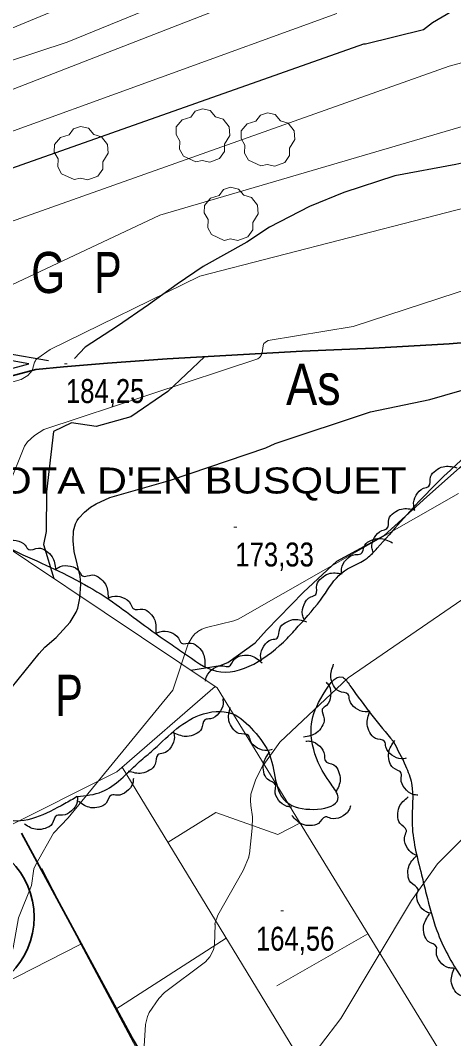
# Model space of a CAD drawing. Extents: x 483847 to 488453, y 4383581 to 4386795.
# Drawn here: x 484564.9 to 484722.9, y 4384859.8 to 4385231.8 of the extents above; entities that cross this region are included whole.
import ezdxf
from ezdxf.enums import TextEntityAlignment as Align

# ---------------------------------------------------------------- set-up
doc = ezdxf.new("R2010")
doc.units = 0
doc.header["$LTSCALE"] = 3.8
doc.linetypes.add('LONG_DASHED', pattern=[7.5, 6, -1.5])
doc.linetypes.add('MEDIUM_DASHED', pattern=[4.5, 3, -1.5])
for name, color, linetype, lineweight in [('25', 7, 'LONG_DASHED', 25), ('27', 7, 'Continuous', 25), ('29', 7, 'Continuous', 13), ('38', 7, 'Continuous', 25), ('51', 7, 'Continuous', 13), ('6', 7, 'Continuous', 35), ('7', 7, 'Continuous', 13), ('8', 7, 'Continuous', 25), ('9', 7, 'Continuous', 13)]:
    doc.layers.add(name, color=color, linetype=linetype, lineweight=lineweight)
doc.layers.add('31', color=7, linetype='Continuous')
doc.layers.add('5', color=7, linetype='Continuous')

msp = doc.modelspace()

# ---------------------------------------------------------------- linework, layer by layer
at = {"layer": '25'}
for points in [[(484744.44, 4385184.53), (484734, 4385181.44), (484723.74, 4385179.06), (484701.41, 4385174.97), (484682.91, 4385168.93), (484670.34, 4385163.77), (484655.79, 4385156.28), (484647.45, 4385150.74), (484631.56, 4385141.82), (484622.13, 4385135.45), (484611.64, 4385127.81), (484600.31, 4385120.09), (484588.51, 4385112.44), (484584.62, 4385108.22)], [(484697.53, 4385043.59), (484713.19, 4385057.72), (484725, 4385068.37), (484738.93, 4385080.47), (484742.6, 4385083.33), (484759.76, 4385096.91), (484768.44, 4385105.31), (484785.43, 4385118.09)], [(484632.01, 4385108.9), (484618.69, 4385096.14), (484605.21, 4385086.95), (484592.55, 4385083.44), (484583.56, 4385084.74), (484577.01, 4385081.55), (484574.39, 4385059.51), (484574.32, 4385045.07), (484573.37, 4385040.36), (484577.15, 4385027.85)], [(484627.12, 4384994.38), (484637.82, 4384996.16), (484640.58, 4384997.21), (484650.58, 4385004.37), (484654.69, 4385009.08), (484668.18, 4385022.91), (484680.36, 4385034.21), (484697.56, 4385043.61)]]:
    msp.add_lwpolyline(points, dxfattribs=at)
at = {"layer": '27'}
for points in [[(484126.09, 4384902.79), (484170.42, 4384940.62), (484186.72, 4384951.71), (484191.28, 4384949.75), (484195.85, 4384942.58), (484195.2, 4384850.61), (484198.46, 4384849.31), (484203.02, 4384849.96), (484206.93, 4384851.91), (484210.19, 4384864.31), (484210.19, 4384911.92), (484211.5, 4384943.23), (484214.1, 4384965.41), (484221.93, 4384987.58), (484217.36, 4384992.8), (484210.19, 4384992.8), (484135.22, 4384984.97), (484130.65, 4384988.89), (484126.09, 4384997.37), (484121.53, 4385047.59), (484126.09, 4385059.33), (484133.91, 4385067.16), (484151.52, 4385069.77), (484197.15, 4385061.94), (484225.84, 4385054.77), (484236.92, 4385050.2), (484251.92, 4385040.42), (484272.13, 4385031.28), (484285.82, 4385029.98), (484298.2, 4385029.33), (484332.11, 4385039.76), (484352.32, 4385052.16), (484358.18, 4385050.2), (484379.05, 4385045.63), (484396, 4385044.98), (484413.6, 4385057.38), (484413.6, 4385076.29), (484415.56, 4385110.21), (484421.42, 4385117.38), (484434.46, 4385125.86), (484452.06, 4385127.17), (484517.26, 4385131.08), (484535.51, 4385145.43), (484539.43, 4385153.26), (484534.21, 4385163.04), (484527.69, 4385172.17), (484530.3, 4385183.26), (484560.29, 4385234.79), (484583.76, 4385251.75), (484588.32, 4385252.4), (484664.6, 4385247.83), (484699.15, 4385252.4), (484722.1, 4385262.06)], [(484700.82, 4384968.46), (484705.41, 4384959.43), (484707.55, 4384953.09), (484707.74, 4384939), (484711.22, 4384919.64), (484712.92, 4384912.69), (484716.8, 4384899.3), (484725.74, 4384882.24), (484736.07, 4384869.4), (484745.06, 4384860.93), (484750.28, 4384857.29), (484764, 4384859.06), (484770.61, 4384868.01), (484777.26, 4384873.01), (484781.91, 4384878.36), (484796.36, 4384884.03), (484807.44, 4384882.61), (484816.96, 4384899.83), (484823.17, 4384919.01), (484826.91, 4384930.91), (484828.12, 4384939.98), (484830.31, 4384967.09), (484821.85, 4384985.57), (484819.78, 4384989.11), (484816.96, 4385006.72), (484804.17, 4385008.65), (484792.01, 4385000.71), (484785.16, 4385000.41), (484783.76, 4385012.32), (484786.61, 4385017.19), (484802.93, 4385029.89), (484816.99, 4385036.63), (484831.62, 4385042.77), (484831.85, 4385052.42), (484828.77, 4385053.4), (484819, 4385062.66), (484818.83, 4385065.3), (484812.25, 4385067.05), (484801.05, 4385062.91), (484791.28, 4385056.88), (484772.36, 4385043.62), (484767.88, 4385041.12), (484748.05, 4385041.41), (484745.09, 4385048.67), (484744.52, 4385049.12), (484744.55, 4385052.7), (484748.79, 4385058.77), (484748.64, 4385063.3), (484740.19, 4385063.82), (484742.63, 4385070.57), (484763.21, 4385085.99), (484768.65, 4385092.72), (484762.05, 4385095.21), (484749.87, 4385090.39), (484739.63, 4385082.24), (484731.52, 4385075.98), (484695.06, 4385038.96)], [(484708.79, 4385052.9), (484708.34, 4385054.62), (484709.24, 4385058.3), (484711.91, 4385060.86), (484713.83, 4385061.57), (484714.51, 4385065.06), (484716.38, 4385067.39), (484719.08, 4385068.74), (484724.03, 4385068.36)], [(484693.57, 4385037.45), (484693.12, 4385039.17), (484694.02, 4385042.85), (484696.69, 4385045.4), (484698.61, 4385046.12), (484699.29, 4385049.61), (484701.16, 4385051.93), (484703.86, 4385053.28), (484708.81, 4385052.9)], [(484585.59, 4384948.21), (484580.97, 4384945.58), (484559.8, 4384939.88), (484549.69, 4384946.4), (484536.11, 4384951.35), (484524.15, 4384948.87), (484511.2, 4384941.93), (484493.5, 4384930.76), (484470.97, 4384918.5), (484448.03, 4384909.24), (484426.95, 4384899.71), (484410.49, 4384892.92), (484385.23, 4384895.42), (484388.62, 4384909.57), (484391.63, 4384936.1), (484393.56, 4384945.05), (484404.24, 4384952.03), (484417.14, 4384934.99), (484427.13, 4384928.88), (484438.84, 4384933.79), (484461.12, 4384944.82), (484483.93, 4384957.41), (484496.79, 4384964.37), (484506.7, 4384969.76), (484524.49, 4384977.21), (484535.34, 4384990.46), (484526.45, 4385001.52), (484515.95, 4385002.96), (484498.76, 4384998.27), (484491.46, 4385002.45), (484491.28, 4385010.27), (484510.27, 4385023.11), (484522.64, 4385031.97), (484541.56, 4385045.7), (484558.82, 4385039.91), (484572.59, 4385033.52), (484597.25, 4385020.22), (484607.27, 4385012.89), (484618.82, 4385004.61), (484624.36, 4385000.79), (484636.37, 4384994.07), (484662.16, 4385005.98), (484666.23, 4385010.44), (484675.39, 4385021.46), (484682.04, 4385029.89), (484691.36, 4385035.38), (484695.06, 4385038.96)], [(484558.14, 4385040.38), (484559.61, 4385041.38), (484563.38, 4385041.73), (484566.67, 4385040.05), (484567.98, 4385038.47), (484571.49, 4385038.98), (484574.31, 4385037.97), (484576.47, 4385035.86), (484577.73, 4385031.07)], [(484682.03, 4385029.7), (484682, 4385031.47), (484683.78, 4385034.83), (484686.99, 4385036.65), (484689.03, 4385036.88), (484690.53, 4385040.1), (484692.91, 4385041.9), (484695.86, 4385042.55), (484700.57, 4385040.98)], [(484577.86, 4385031.31), (484579.38, 4385032.22), (484583.17, 4385032.37), (484586.36, 4385030.51), (484587.58, 4385028.86), (484591.12, 4385029.18), (484593.88, 4385028.02), (484595.92, 4385025.8), (484596.92, 4385020.94)], [(484668.36, 4385012.98), (484667.76, 4385014.64), (484668.34, 4385018.39), (484670.78, 4385021.16), (484672.64, 4385022.04), (484673.01, 4385025.58), (484674.67, 4385028.06), (484677.25, 4385029.63), (484682.21, 4385029.68)], [(484596.75, 4385020.63), (484598.38, 4385021.33), (484602.16, 4385020.96), (484605.06, 4385018.68), (484606.05, 4385016.88), (484609.6, 4385016.71), (484612.17, 4385015.2), (484613.89, 4385012.71), (484614.22, 4385007.76)], [(484652.85, 4384997.87), (484652.52, 4384999.61), (484653.71, 4385003.22), (484656.56, 4385005.56), (484658.54, 4385006.12), (484659.47, 4385009.55), (484661.51, 4385011.73), (484664.31, 4385012.87), (484669.22, 4385012.12)], [(484614.19, 4385007.71), (484615.8, 4385008.47), (484619.58, 4385008.24), (484622.57, 4385006.07), (484623.62, 4385004.31), (484627.17, 4385004.27), (484629.8, 4385002.85), (484631.61, 4385000.43), (484632.12, 4384995.49)], [(484632.43, 4384990.4), (484632.81, 4384992.13), (484635.31, 4384994.99), (484638.86, 4384996.02), (484640.9, 4384995.77), (484643.1, 4384998.56), (484645.83, 4384999.76), (484648.85, 4384999.72), (484653.07, 4384997.1)], [(484692.39, 4384979.38), (484690.63, 4384979.16), (484687.1, 4384980.55), (484684.94, 4384983.54), (484684.49, 4384985.55), (484681.12, 4384986.69), (484679.07, 4384988.85), (484678.1, 4384991.72), (484679.14, 4384996.56)], [(484585.59, 4384948.21), (484594.7, 4384950.05), (484607.73, 4384960.45), (484612.68, 4384964.74), (484630.28, 4384977.98), (484642.06, 4384978.57), (484649.94, 4384972.27), (484655.9, 4384963.29), (484663.95, 4384945.01), (484680.79, 4384948.01), (484678.22, 4384952.8), (484673.51, 4384960.71), (484670.94, 4384973.59), (484674.44, 4384984.01), (484682.46, 4384991.8), (484685.09, 4384988.84), (484700.82, 4384968.46)], [(484676.39, 4384990.05), (484677.47, 4384988.64), (484678.03, 4384984.89), (484676.53, 4384981.52), (484675.02, 4384980.13), (484675.72, 4384976.64), (484674.87, 4384973.78), (484672.88, 4384971.5), (484668.16, 4384969.98)], [(484638.7, 4384983.94), (484638.85, 4384982.17), (484637.31, 4384978.7), (484634.23, 4384976.66), (484632.21, 4384976.3), (484630.94, 4384972.98), (484628.68, 4384971.02), (484625.78, 4384970.17), (484620.98, 4384971.41)], [(484656.73, 4384965.48), (484655.02, 4384965.04), (484651.34, 4384965.97), (484648.81, 4384968.65), (484648.1, 4384970.58), (484644.62, 4384971.28), (484642.3, 4384973.17), (484640.97, 4384975.88), (484641.39, 4384980.83)], [(484705.64, 4384962.21), (484703.88, 4384961.99), (484700.36, 4384963.38), (484698.19, 4384966.37), (484697.74, 4384968.38), (484694.37, 4384969.51), (484692.32, 4384971.68), (484691.35, 4384974.55), (484692.39, 4384979.39)], [(484620.73, 4384971.72), (484621.06, 4384969.98), (484619.86, 4384966.37), (484617, 4384964.04), (484615.03, 4384963.48), (484614.08, 4384960.05), (484612.03, 4384957.88), (484609.23, 4384956.75), (484604.33, 4384957.52)], [(484668.97, 4384968.5), (484670.74, 4384968.49), (484674.06, 4384966.65), (484675.82, 4384963.41), (484676.01, 4384961.37), (484679.2, 4384959.8), (484680.96, 4384957.39), (484681.55, 4384954.42), (484679.89, 4384949.75)], [(484709.88, 4384948.77), (484708.13, 4384949.01), (484705.07, 4384951.26), (484703.75, 4384954.71), (484703.83, 4384956.76), (484700.87, 4384958.73), (484699.44, 4384961.35), (484699.24, 4384964.37), (484701.49, 4384968.78)], [(484663.8, 4384944.38), (484662.05, 4384944.67), (484659.06, 4384946.99), (484657.82, 4384950.47), (484657.95, 4384952.52), (484655.04, 4384954.56), (484653.68, 4384957.22), (484653.55, 4384960.24), (484655.91, 4384964.6)], [(484606.12, 4384954.87), (484605.89, 4384953.11), (484603.64, 4384950.06), (484600.2, 4384948.72), (484598.14, 4384948.8), (484596.18, 4384945.84), (484593.56, 4384944.4), (484590.55, 4384944.19), (484586.13, 4384946.44)], [(484585.7, 4384948.01), (484585.6, 4384946.23), (484583.58, 4384943.02), (484580.25, 4384941.43), (484578.2, 4384941.36), (484576.46, 4384938.26), (484573.96, 4384936.63), (484570.96, 4384936.2), (484566.39, 4384938.11)], [(484709.71, 4384926.71), (484708.06, 4384927.35), (484705.62, 4384930.27), (484705.15, 4384933.93), (484705.71, 4384935.9), (484703.3, 4384938.51), (484702.54, 4384941.4), (484703.05, 4384944.38), (484706.29, 4384948.14)], [(484685.34, 4384944.88), (484684.7, 4384943.22), (484681.8, 4384940.77), (484678.14, 4384940.28), (484676.17, 4384940.83), (484673.57, 4384938.4), (484670.69, 4384937.62), (484667.71, 4384938.12), (484663.93, 4384941.33)], [(484714.7, 4384905.6), (484713, 4384906.1), (484710.32, 4384908.79), (484709.53, 4384912.4), (484709.92, 4384914.41), (484707.29, 4384916.8), (484706.28, 4384919.61), (484706.53, 4384922.62), (484709.43, 4384926.65)], [(484722.84, 4384885.51), (484721.08, 4384885.72), (484717.99, 4384887.93), (484716.61, 4384891.35), (484716.67, 4384893.4), (484713.67, 4384895.32), (484712.21, 4384897.92), (484711.96, 4384900.94), (484714.14, 4384905.39)], [(484736.12, 4384868.22), (484734.36, 4384868.04), (484730.86, 4384869.5), (484728.75, 4384872.53), (484728.34, 4384874.55), (484725, 4384875.75), (484722.99, 4384877.96), (484722.07, 4384880.84), (484723.21, 4384885.67)]]:
    msp.add_spline(points, degree=3, dxfattribs=at)
at = {"layer": '29'}
for points in [[(484628.88, 4385180.03), (484624.34, 4385182.15), (484622.93, 4385184.69), (484623.03, 4385187.67), (484621.66, 4385190.08), (484621.7, 4385192.83), (484623.86, 4385195.43), (484627.05, 4385196.43), (484628.7, 4385198.62), (484631.27, 4385199.45), (484634.13, 4385198.8), (484636.08, 4385196.53), (484638.89, 4385195.71), (484641.02, 4385192.86), (484641.26, 4385189.73), (484639.38, 4385186.58), (484639.38, 4385183.9), (484637.56, 4385181.29), (484633.94, 4385179.95), (484631.17, 4385180.58)], [(484652.61, 4385178.58), (484648.07, 4385180.7), (484646.66, 4385183.24), (484646.76, 4385186.22), (484645.39, 4385188.63), (484645.43, 4385191.38), (484647.59, 4385193.98), (484650.78, 4385194.98), (484652.43, 4385197.17), (484655, 4385198), (484657.86, 4385197.35), (484659.81, 4385195.08), (484662.62, 4385194.26), (484664.75, 4385191.41), (484664.99, 4385188.28), (484663.11, 4385185.13), (484663.11, 4385182.45), (484661.29, 4385179.84), (484657.67, 4385178.5), (484654.9, 4385179.13)], [(484584.49, 4385173.58), (484579.95, 4385175.7), (484578.54, 4385178.24), (484578.64, 4385181.22), (484577.27, 4385183.63), (484577.31, 4385186.38), (484579.47, 4385188.98), (484582.66, 4385189.98), (484584.31, 4385192.17), (484586.88, 4385193), (484589.74, 4385192.35), (484591.69, 4385190.08), (484594.5, 4385189.26), (484596.63, 4385186.41), (484596.87, 4385183.28), (484594.99, 4385180.13), (484594.99, 4385177.45), (484593.17, 4385174.84), (484589.55, 4385173.5), (484586.78, 4385174.13)], [(484639.2, 4385151.38), (484634.66, 4385153.5), (484633.25, 4385156.04), (484633.35, 4385159.02), (484631.98, 4385161.43), (484632.02, 4385164.18), (484634.18, 4385166.78), (484637.37, 4385167.78), (484639.02, 4385169.97), (484641.59, 4385170.8), (484644.45, 4385170.15), (484646.4, 4385167.88), (484649.21, 4385167.06), (484651.34, 4385164.21), (484651.58, 4385161.08), (484649.7, 4385157.93), (484649.7, 4385155.25), (484647.88, 4385152.64), (484644.26, 4385151.3), (484641.49, 4385151.93)]]:
    msp.add_lwpolyline(points, close=True, dxfattribs=at)
at = {"layer": '38'}
for points in [[(484575.11, 4385107.35), (484559.72, 4385110.12), (484547.39, 4385113.14), (484533.67, 4385115.32), (484529.84, 4385115.71), (484517.23, 4385115.6), (484504.96, 4385114.38), (484493.01, 4385111.43), (484484.54, 4385110.72)], [(484512.21, 4385070.54), (484510.07, 4385069.71), (484503.45, 4385067.95), (484494.86, 4385067.66), (484487.56, 4385070.75), (484485.77, 4385077.78), (484486.76, 4385083.45), (484492.78, 4385090.14), (484498.31, 4385095.54), (484503.01, 4385097.53), (484512.33, 4385099.57), (484524.48, 4385100.9), (484529.91, 4385101.49), (484544.21, 4385102.32), (484552.12, 4385102.97), (484559.47, 4385104.04), (484567.95, 4385106.3)]]:
    msp.add_lwpolyline(points, dxfattribs=at)
at = {"layer": '38', "linetype": 'MEDIUM_DASHED'}
msp.add_lwpolyline([(484567.95, 4385106.3), (484559.24, 4385107.87), (484546.93, 4385110.88), (484533.37, 4385113.04), (484529.73, 4385113.41), (484517.36, 4385113.3), (484505.36, 4385112.1), (484493.39, 4385109.15), (484484.73, 4385108.42)], dxfattribs=at)
at = {"layer": '51'}
for p, q in [((484691.61, 4384898.13), (484658.41, 4384879.16)), ((484640, 4384896.53), (484599.66, 4384870.56))]:
    msp.add_line(p, q, dxfattribs=at)
for points in [[(484526.51, 4385061.76), (484636.63, 4384988), (484717.12, 4384856.42)], [(484635.97, 4384988.45), (484600.12, 4384957.29), (484558.58, 4384936.42), (484473.09, 4384890.68), (484400.03, 4384856.08)], [(484647.76, 4384806.59), (484681.62, 4384827.95), (484602.07, 4384958.99)], [(484618.75, 4384931.53), (484636.16, 4384942.46), (484658.85, 4384934.34), (484666.88, 4384938.56)], [(484481.98, 4384840.82), (484586.98, 4384894.3), (484572.68, 4384921.94)], [(484497.98, 4384788.65), (484610.92, 4384849.44), (484586.98, 4384894.3)]]:
    msp.add_lwpolyline(points, dxfattribs=at)
at = {"layer": '6'}
for points in [[(484721.33, 4385113.65), (484764.31, 4385117.19), (484778.74, 4385117.71), (484800.28, 4385118.92), (484831.98, 4385121), (484878.85, 4385124.3), (484916.93, 4385127.45), (484967.4, 4385129.79), (485007.23, 4385131.89)], [(484560.92, 4385101.66), (484570.5, 4385104.22), (484580.6, 4385105.21), (484596.61, 4385106.51), (484618.44, 4385108.14), (484667.62, 4385110.91), (484693.66, 4385111.99), (484721.33, 4385113.65)], [(484565.32, 4384934.84), (484605.7, 4384860.08), (484675.78, 4384741.99), (484695.63, 4384706.66), (484712.65, 4384678.75), (484716.37, 4384675.91), (484718.11, 4384675.18), (484727.45, 4384676.03), (484733.24, 4384679.19), (484746.86, 4384686.49), (484788.02, 4384709.66)]]:
    msp.add_lwpolyline(points, dxfattribs=at)
msp.add_circle((484540.83, 4384904.23), 29.1, dxfattribs=at)
at = {"layer": '7'}
for p, q in [((484581.01, 4385106.36), (484582.01, 4385106.36)), ((484642.79, 4385046.65), (484643.79, 4385046.65)), ((484659.88, 4384906.55), (484660.88, 4384906.55))]:
    msp.add_line(p, q, dxfattribs=at)
at = {"layer": '8'}
for points in [[(485053.89, 4385382.33), (484777.81, 4385260.43), (484759.84, 4385250.4), (484727.87, 4385238.26), (484715.25, 4385230.85), (484711.94, 4385228.29), (484690.83, 4385223.11), (484690.08, 4385223.01), (484473.45, 4385146.49), (484463.01, 4385144.7), (484446.58, 4385144.16), (484436.83, 4385145.34), (484425.84, 4385148.55), (484392.47, 4385165.18), (484371.15, 4385170.67), (484370.47, 4385170.69), (484370.39, 4385170.61)], [(484553.81, 4384978.38), (484571.75, 4385000.45), (484573.8, 4385002.83), (484577.91, 4385006.32), (484583.05, 4385011.95), (484585.25, 4385015.57), (484585.81, 4385017.1), (484586.57, 4385020.66), (484586.95, 4385025.78), (484586.7, 4385028.8), (484584.46, 4385037.78), (484584.09, 4385041.66), (484584.21, 4385045.33), (484585.05, 4385047.87), (484585.65, 4385049.14), (484586.16, 4385049.88), (484588.26, 4385052.16), (484590.52, 4385054), (484592.53, 4385055.22), (484597.48, 4385057.43), (484619.62, 4385063.84), (484654.43, 4385075.61), (484657.79, 4385077.18), (484692.59, 4385088.81), (484714.22, 4385093.26), (484731.5, 4385098.25)]]:
    msp.add_lwpolyline(points, dxfattribs=at)
at = {"layer": '9'}
for points in [[(485054.14, 4385332.87), (484883.38, 4385253.17), (484733.9, 4385195.32), (484615.72, 4385160.61), (484555.4, 4385132.21), (484513.55, 4385120.77), (484510.75, 4385119.2), (484509.92, 4385118.55), (484509.52, 4385118.09), (484508.92, 4385117.06), (484508.44, 4385115.95), (484508.26, 4385115.37), (484508.11, 4385114.44), (484508, 4385112.83), (484507.78, 4385111.91), (484507.49, 4385111.22), (484507.29, 4385110.87), (484506.84, 4385110.28), (484502.03, 4385107.06), (484494.64, 4385103.71), (484490.58, 4385102.53)], [(484511.9, 4385074.36), (484512.09, 4385075.75), (484512.35, 4385076.46), (484513.05, 4385077.85), (484514.47, 4385079.95), (484515.92, 4385081.53), (484518.41, 4385083.62), (484521.57, 4385085.68), (484534.81, 4385092.07), (484565.15, 4385100.6), (484567.56, 4385102.05), (484569.26, 4385103.99), (484569.34, 4385104.18), (484570.1, 4385106.91), (484570.36, 4385107.45), (484570.53, 4385107.71), (484570.88, 4385108.1), (484571.29, 4385108.43), (484575.81, 4385111.51), (484630.36, 4385138.36), (484767.17, 4385173.58), (485050.82, 4385305.37)], [(484646.79, 4385264.26), (484558.06, 4385227.37), (484509.35, 4385211.29), (484465.02, 4385190.92), (484452.05, 4385187.63), (484429.19, 4385186.9), (484416.26, 4385188.56), (484412.17, 4385190.04), (484408.53, 4385191.88), (484373.02, 4385222.21), (484362.43, 4385234.72)], [(484485.13, 4385176.62), (484688.37, 4385255.87)], [(484505.8, 4385198.77), (484581.9, 4385223.83), (484648.43, 4385251.07)], [(484395.02, 4385171.96), (484395.72, 4385171.4), (484398.52, 4385170.1), (484415.91, 4385160.74), (484421.74, 4385158.49), (484424.42, 4385157.33), (484426.3, 4385156.85), (484427.85, 4385156.28), (484434.73, 4385154.53), (484446.09, 4385153.23), (484459.9, 4385154.07), (484462.34, 4385154.56), (484473.69, 4385157.73), (484474.92, 4385158.32), (484476.69, 4385158.96), (484477.85, 4385159.57), (484479.4, 4385160.19), (484487.27, 4385164.18), (484680.28, 4385234.24)], [(484757.4, 4385224.8), (484721.23, 4385215.05), (484476.53, 4385128.11)], [(484780.43, 4385150.78), (484686.32, 4385119.99), (484655.33, 4385114.79), (484654.71, 4385114.51), (484654.12, 4385114.11), (484653.72, 4385113.7), (484653.56, 4385113.43), (484653.39, 4385112.87), (484653.07, 4385110.3), (484652.98, 4385109.94), (484652.76, 4385109.38), (484652.4, 4385108.87), (484652.13, 4385108.59), (484651.51, 4385108.08), (484573.46, 4385082.32), (484570.02, 4385080.12), (484567.52, 4385077.87), (484566.35, 4385076.26), (484560.4, 4385061.4)], [(484507.37, 4384859.73), (484551.37, 4384876.96), (484552.77, 4384877.94), (484554.87, 4384879.92), (484556.57, 4384882.14), (484561.49, 4384890.74), (484562.24, 4384893.05), (484564.15, 4384904.01), (484568.91, 4384915.8), (484569.85, 4384921.83), (484570.51, 4384923.41), (484576.94, 4384934.93), (484582.28, 4384940.48), (484620.44, 4384987.15), (484626.11, 4385004.03), (484627.56, 4385006.48), (484628.56, 4385007.65), (484629.35, 4385008.33), (484629.62, 4385008.52), (484631.06, 4385009.35), (484632.76, 4385010), (484642.78, 4385012.43), (484644.37, 4385013.07), (484724.63, 4385058.95)], [(484748.82, 4385035.87), (484684.43, 4384991.59), (484659.54, 4384968.17), (484653.04, 4384959.06), (484650.82, 4384954.64), (484649.27, 4384950.27), (484648.99, 4384949.18), (484648.84, 4384946.81), (484648.97, 4384945.03), (484649.54, 4384940.81), (484649.56, 4384940.45), (484649.48, 4384936.99), (484649.46, 4384936.81), (484649.46, 4384936.77), (484649.46, 4384936.65), (484648.5, 4384927.34), (484648.27, 4384926.44), (484648.19, 4384926.26), (484648.14, 4384926.23), (484648.12, 4384926.22), (484648.13, 4384926.21), (484648.17, 4384926.17), (484646.11, 4384921.25), (484636.94, 4384904.89), (484635.85, 4384901.71), (484635.85, 4384901.69), (484635.89, 4384901.54), (484635.9, 4384901.51), (484635.7, 4384894.07), (484635.38, 4384892.29), (484634, 4384889.67), (484632.42, 4384887.94), (484617.52, 4384876.62), (484615.35, 4384874.44), (484611.86, 4384869.38), (484611.22, 4384867.89), (484610.48, 4384864.99), (484609.62, 4384851.22)], [(484745.13, 4384953.01), (484742.52, 4384949.21), (484717.09, 4384923.73), (484707.54, 4384910.25), (484681.81, 4384867.19), (484666.9, 4384847.65)]]:
    msp.add_lwpolyline(points, dxfattribs=at)

# ---------------------------------------------------------------- texts
at = {"layer": '31'}
for s, width, p in [('G', 0.8, (484575.08, 4385132.17)), ('P', 0.75, (484596.82, 4385132.16)), ('As', 0.85, (484671.75, 4385091.31)), ('P', 0.75, (484582.64, 4384977.73))]:
    msp.add_text(s, height=15, dxfattribs=dict(at, width=width)).set_placement(p, align=Align.CENTER)
at = {"layer": '5', "width": 1.2}
msp.add_text("ROTA D'EN BUSQUET", height=9.5, dxfattribs=at).set_placement((484546.18, 4385058.94))
at = {"layer": '7', "width": 0.8}
for s, p in [('184,25', (484581.51, 4385091.99)), ('173,33', (484643.29, 4385032.28)), ('164,56', (484650.79, 4384891.95))]:
    msp.add_text(s, height=8.75, dxfattribs=at).set_placement(p)

doc.saveas('drawing.dxf')
